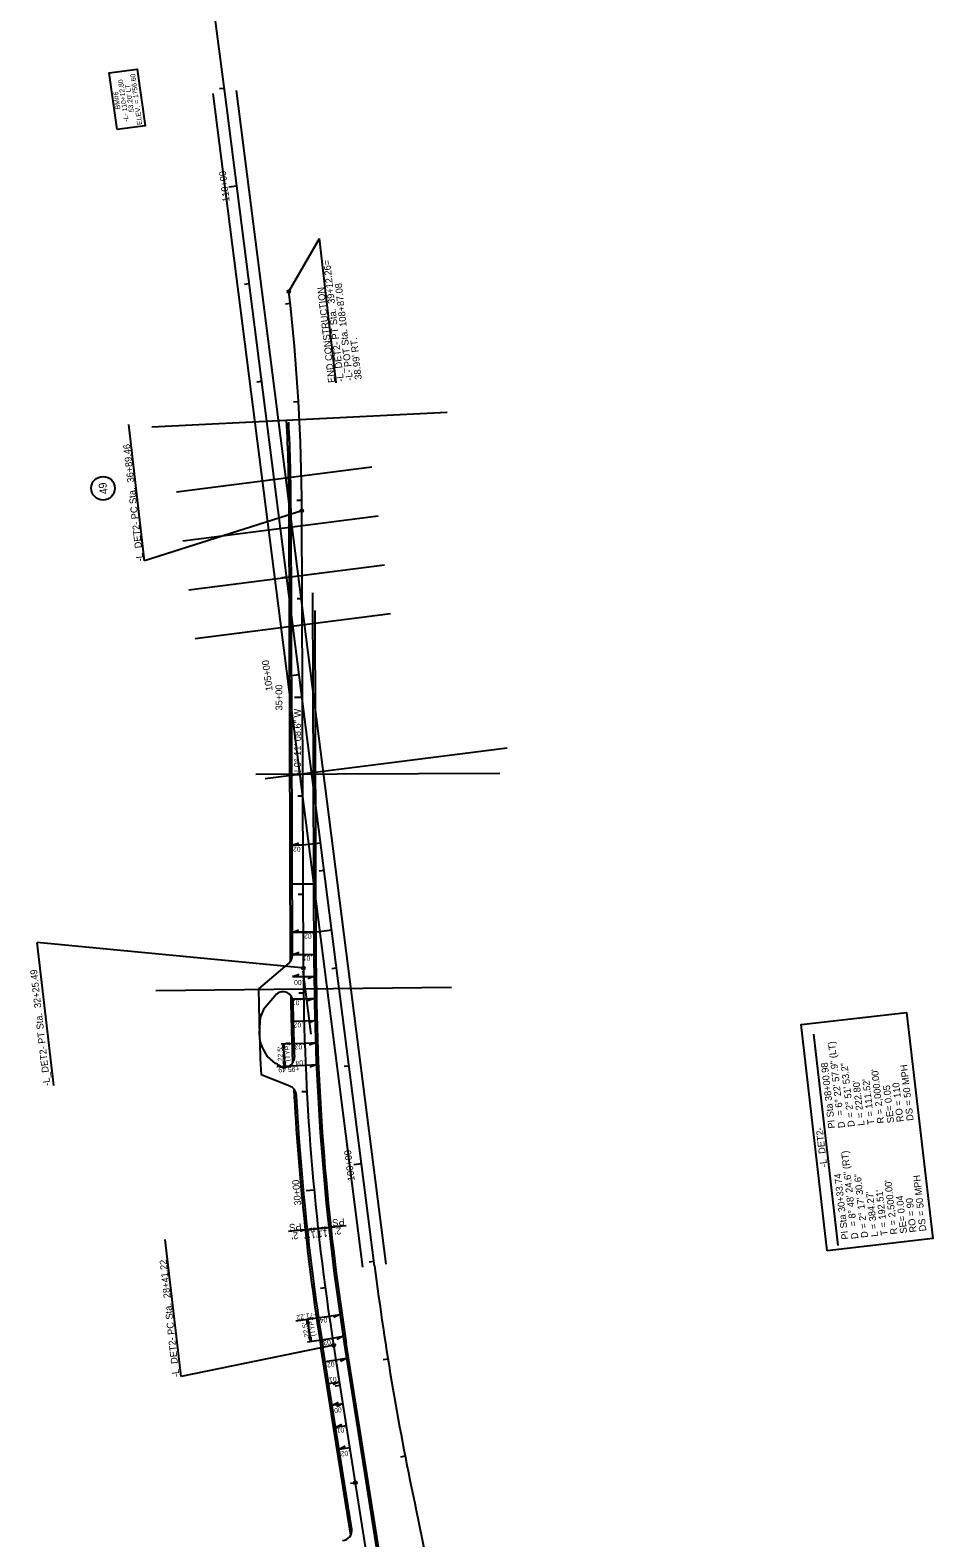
# Model space of a CAD drawing. Extents: x 473658 to 481584, y 489119 to 506230.
# Drawn here: x 477863 to 478779, y 496238 to 497767 of the extents above; entities that cross this region are included whole.
import ezdxf

# ---------------------------------------------------------------- set-up
doc = ezdxf.new("R2010")
doc.units = 0
for name, color, linetype in [('Default', 7, 'Continuous'), ('Prop Dimension', 7, 'Continuous'), ('Prop EOT', 7, 'Continuous'), ('Prop Grid Mask', 7, 'Continuous'), ('Prop Horizontal Alignment', 7, 'Continuous'), ('Prop Horizontal Alignment Curve and Spiral Data', 7, 'Continuous'), ('Prop Horizontal Alignment Direction Label', 7, 'Continuous'), ('Prop Horizontal Alignment Station Label', 7, 'Continuous'), ('Prop Horizontal Alignment Tick Label', 7, 'Continuous'), ('Prop Horizontal Alignment Tick Large', 7, 'Continuous'), ('Prop Horizontal Alignment Tick Small', 7, 'Continuous'), ('Prop Paved Shoulder', 7, 'Continuous'), ('Prop Superelevation  Arrow CELL', 7, 'Continuous'), ('Prop Superelevation Label', 7, 'Continuous'), ('Scratch_Level_5', 7, 'Continuous'), ('Scratch_Level_6', 7, 'Continuous'), ('Scratch_Level_9', 7, 'Continuous')]:
    doc.layers.add(name, color=color, linetype=linetype)

msp = doc.modelspace()

# ---------------------------------------------------------------- linework, layer by layer
at = {"layer": 'Default'}
msp.add_line((477937, 497302.6), (477937, 497302.6), dxfattribs=at)
msp.add_circle((477937, 497302.6), 12, dxfattribs=at)
at = {"layer": 'Prop Dimension'}
for p, q in [((478142.2, 496550.2), (478125, 496548.5)), ((478166.1, 496552.6), (478144.2, 496550.4)), ((478183.8, 496554.4), (478168, 496552.8))]:
    msp.add_line(p, q, dxfattribs=at)
for points in [[(478137.6, 496550.5), (478142.2, 496550.2), (478137.8, 496548.9), (478138.3, 496549.8)], [(478148.7, 496550.1), (478144.2, 496550.4), (478148.6, 496551.6), (478148.1, 496550.8)], [(478150.6, 496551.8), (478155.1, 496551.5), (478150.7, 496550.2), (478151.2, 496551.1)], [(478159.7, 496551.2), (478155.1, 496551.5), (478159.5, 496552.7), (478159, 496551.9)], [(478161.5, 496552.9), (478166.1, 496552.6), (478161.6, 496551.3), (478162.1, 496552.2)], [(478172.6, 496552.5), (478168, 496552.8), (478172.5, 496554), (478172, 496553.2)]]:
    msp.add_lwpolyline(points, close=True, dxfattribs=at)
at = {"layer": 'Prop EOT'}
for p, q in [((478129.2, 496828.8), (478127.7, 497279.7)), ((478151.2, 496815.8), (478150, 497196.6)), ((478125.7, 496821.2), (478094.8, 496794.9)), ((478113.1, 496789.4), (478099.8, 496773.7)), ((478114.1, 496718.2), (478112, 496719)), ((478126.6, 496696), (478097.3, 496707.6)), ((478184, 496280.1), (478160.1, 496431.4)), ((478319.9, 495562.1), (478181.8, 496434.9)), ((478189.3, 496246.6), (478184, 496280.1))]:
    msp.add_line(p, q, dxfattribs=at)
for points in [[(478099.8, 496773.7), (478096.6, 496766.2)], [(478112, 496719), (478103.8, 496726.1), (478102.4, 496728.3), (478099, 496734.4), (478096.3, 496741.3), (478095.7, 496749.8), (478096.6, 496766.2)]]:
    msp.add_lwpolyline(points, dxfattribs=at)
for centre, radius, start, end in [((476138.7, 497273.3), 1989, 0.1857, 2.7759), ((478119.2, 496828.8), 10, 310.4144, 0.1857), ((480640.2, 496823.9), 2489, 180.1857, 188.9925), ((480640.6, 496823.9), 2546, 180.6537, 182.6189), ((478119.6, 496781.8), 10, 0.9568, 130.4144), ((480640.2, 496823.9), 2511, 180.8982, 182.2432), ((478121.2, 496725.2), 10, 225.0261, 2.2432), ((478123, 496686.7), 10, 3.1201, 68.4309), ((480640.2, 496823.9), 2511, 183.1201, 188.9925), ((478179.5, 496245.1), 10, 272.076, 8.9925)]:
    msp.add_arc(centre, radius, start, end, dxfattribs=at)
at = {"layer": 'Prop Grid Mask'}
for points in [[(477951.2, 497666.5), (477943.2, 497723.9), (477971.6, 497727.9), (477979.6, 497670.4)], [(478671.8, 496528.9), (478645.2, 496758.4), (478752.3, 496770.8), (478778.9, 496541.3)]]:
    msp.add_lwpolyline(points, close=True, dxfattribs=at)
at = {"layer": 'Prop Horizontal Alignment'}
for p, q in [((478212.5, 496513.8), (478060.5, 497704.7)), ((478140.2, 496815.8), (478138.7, 497279.8)), ((478309.1, 495560.4), (478171, 496433.1)), ((478193, 496293.7), (478188.1, 496292.9)), ((478263.7, 496222.6), (478254.9, 496265.4))]:
    msp.add_line(p, q, dxfattribs=at)
for centre, radius, start, end in [((456237.5, 494918.9), 22000, 7.27466, 7.92268), ((476138.7, 497273.3), 2000, 0.1857, 6.5685), ((480640.2, 496823.9), 2500, 180.1857, 188.9925), ((481188.3, 496893.6), 3000, 187.2747, 192.0883)]:
    msp.add_arc(centre, radius, start, end, dxfattribs=at)
at = {"layer": 'Prop Horizontal Alignment Station Label'}
for p, q in [((478125.6, 497502.1), (478156.6, 497556.1)), ((478173.5, 497409.5), (478156.6, 497556.1)), ((477979, 497228.9), (477963.1, 497367.2)), ((478138.7, 497279.8), (477979, 497228.9)), ((478141.7, 496815.8), (477870.3, 496841.7)), ((477887, 496696.7), (477870.3, 496841.7)), ((478657.8, 496748.8), (478682.6, 496534.4)), ((478016.1, 496401.3), (478000.1, 496540.3)), ((478171, 496433.1), (478016.1, 496401.3))]:
    msp.add_line(p, q, dxfattribs=at)
for centre in [(478125.6, 497502.1), (478138.7, 497279.8), (478140.2, 496815.8), (478171, 496433.1), (478171, 496433.1), (478193, 496293.7)]:
    msp.add_circle(centre, 1.5, dxfattribs=at)
at = {"layer": 'Prop Horizontal Alignment Tick Large'}
for p, q in [((478072.7, 497609.1), (478064.7, 497608.1)), ((478136, 497113.2), (478128, 497112.2)), ((478139.4, 497090.3), (478131.4, 497090.3)), ((478199.3, 496617.2), (478191.3, 496616.2)), ((478151.1, 496590.6), (478143.2, 496589.9))]:
    msp.add_line(p, q, dxfattribs=at)
at = {"layer": 'Prop Horizontal Alignment Tick Small'}
for p, q in [((478060, 497708.3), (478055, 497707.7)), ((478085.3, 497509.9), (478080.4, 497509.3)), ((478127, 497489.9), (478122, 497489.3)), ((478098, 497410.8), (478093, 497410.1)), ((478135.3, 497390.2), (478130.3, 497389.9)), ((478110.6, 497311.6), (478105.7, 497310.9)), ((478138.7, 497290.3), (478133.7, 497290.3)), ((478123.3, 497212.4), (478118.3, 497211.7)), ((478139, 497190.3), (478134, 497190.3)), ((478148.6, 497014), (478143.7, 497013.3)), ((478139.7, 496990.3), (478134.7, 496990.3)), ((478161.3, 496914.8), (478156.3, 496914.1)), ((478140, 496890.3), (478135, 496890.3)), ((478174, 496815.6), (478169, 496815)), ((478140.5, 496790.3), (478135.5, 496790.2)), ((478186.6, 496716.4), (478181.7, 496715.8)), ((478143.8, 496690.4), (478138.8, 496690.1)), ((478211.9, 496518), (478207, 496517.4)), ((478162.5, 496491.3), (478157.5, 496490.6)), ((478226.1, 496419), (478221.2, 496418.2)), ((478177.4, 496392.4), (478172.5, 496391.6)), ((478243.6, 496320.6), (478238.7, 496319.6)), ((478193, 496293.7), (478188.1, 496292.9))]:
    msp.add_line(p, q, dxfattribs=at)
at = {"layer": 'Prop Paved Shoulder'}
for p, q in [((478127.2, 496822.8), (478125.7, 497279.7)), ((478153.2, 496815.8), (478152.1, 497178.5)), ((478183, 496273.9), (478158.1, 496431.1)), ((478321.9, 495562.4), (478183.8, 496435.2)), ((478188.3, 496240.4), (478183, 496273.9))]:
    msp.add_line(p, q, dxfattribs=at)
for centre, radius, start, end in [((476138.7, 497273.3), 1987, 0.1857, 2.8372), ((480640.2, 496823.9), 2487, 180.1857, 188.9925), ((480640.2, 496823.9), 2513, 180.8202, 182.3798), ((480640.2, 496823.9), 2513, 182.9835, 188.9925)]:
    msp.add_arc(centre, radius, start, end, dxfattribs=at)
at = {"layer": 'Prop Superelevation  Arrow CELL'}
for points in [[(478128.8, 496940.6), (478134.8, 496942.6), (478133.5, 496940.6)], [(478129.1, 496852.2), (478135.1, 496854.2), (478133.7, 496852.2)], [(478129.2, 496829.7), (478135.2, 496831.7), (478133.8, 496829.7)], [(478129.3, 496807.1), (478135.3, 496809.2), (478133.9, 496807.2)], [(478151.3, 496807.3), (478145.3, 496805.2), (478146.7, 496807.3)], [(478151.5, 496784.9), (478145.6, 496782.8), (478146.9, 496784.8)], [(478152, 496762.5), (478146, 496760.3), (478147.4, 496762.4)], [(478119.4, 496734.6), (478120.1, 496739.1), (478120.9, 496734.6), (478120.1, 496735.1)], [(478152.6, 496740.1), (478146.7, 496737.9), (478148, 496739.9)], [(478121.6, 496720.9), (478121, 496716.3), (478120, 496720.8), (478120.8, 496720.3)], [(478153.5, 496717.7), (478147.6, 496715.5), (478148.9, 496717.5)], [(478144.1, 496455), (478144.2, 496459.6), (478145.7, 496455.2), (478144.8, 496455.7)], [(478177.3, 496464.4), (478171.7, 496461.5), (478172.8, 496463.7)], [(478147.8, 496441.7), (478147.7, 496437.1), (478146.2, 496441.5), (478147.1, 496441)], [(478180.7, 496442.2), (478175, 496439.3), (478176.1, 496441.5)], [(478184.2, 496420), (478178.6, 496417.1), (478179.6, 496419.3)], [(478176.8, 496396.1), (478171.2, 496393.2), (478172.3, 496395.4)], [(478169.5, 496372.2), (478175.1, 496375.1), (478174, 496372.9)], [(478180.3, 496373.9), (478174.7, 496371), (478175.8, 496373.2)], [(478173, 496349.9), (478178.6, 496352.8), (478177.6, 496350.7)], [(478176.5, 496327.7), (478182.1, 496330.6), (478181.1, 496328.4)]]:
    msp.add_lwpolyline(points, close=True, dxfattribs=at)
at = {"layer": 'Prop Superelevation Label'}
for p, q in [((478128.8, 496940.6), (478139.8, 496940.7)), ((478129.1, 496852.2), (478151.1, 496852.2)), ((478129.2, 496829.7), (478151.2, 496829.7)), ((478129.3, 496807.1), (478151.3, 496807.3)), ((478129.5, 496784.5), (478140.5, 496784.7)), ((478140.5, 496784.7), (478151.5, 496784.9)), ((478130, 496761.9), (478141, 496762.2)), ((478141, 496762.2), (478152, 496762.5)), ((478117.6, 496738.9), (478141.6, 496739.7)), ((478141.6, 496739.7), (478152.6, 496740.1)), ((478113.4, 496716), (478142.5, 496717.2)), ((478142.5, 496717.2), (478153.5, 496717.7)), ((478132.6, 496457.9), (478166.4, 496462.8)), ((478166.4, 496462.8), (478177.3, 496464.4)), ((478144.5, 496436.6), (478169.8, 496440.5)), ((478169.8, 496440.5), (478180.7, 496442.2)), ((478162.4, 496416.6), (478173.3, 496418.3)), ((478173.3, 496418.3), (478184.2, 496420)), ((478166, 496394.4), (478176.8, 496396.1)), ((478169.5, 496372.2), (478180.3, 496373.9)), ((478173, 496349.9), (478183.9, 496351.7)), ((478176.5, 496327.7), (478187.4, 496329.4))]:
    msp.add_line(p, q, dxfattribs=at)
for centre, start, end in [((479146.7, 496769), 181.6837, 182.9409), ((479161.2, 496603.6), 188.0646, 189.331)]:
    msp.add_arc(centre, 1027.1, start, end, dxfattribs=at)
at = {"layer": 'Scratch_Level_5'}
for p, q in [((477986.5, 497364.8), (478286.1, 497379.7)), ((477990.4, 496793.1), (478290.4, 496796.5))]:
    msp.add_line(p, q, dxfattribs=at)
at = {"layer": 'Scratch_Level_6'}
for p, q in [((478224.4, 496515.3), (478072.4, 497706.2)), ((478200.6, 496512.2), (478048.6, 497703.1)), ((478101.5, 497008), (478347, 497039.3)), ((478092.1, 497012.7), (478339.6, 497013.5)), ((478139.8, 496940.7), (478157.7, 496942.9)), ((478139.8, 496940.7), (478128.8, 496940.6)), ((478151, 496900.9), (478129, 496900.8)), ((478151.1, 496852.2), (478129.1, 496852.2)), ((478151.1, 496852.2), (478169, 496854.5)), ((478148.2, 496748.7), (478140.1, 496812.6))]:
    msp.add_line(p, q, dxfattribs=at)
at = {"layer": 'Scratch_Level_9'}
for p, q in [((478011.4, 497298.9), (478209.8, 497324.2)), ((478017.8, 497249.3), (478216.2, 497274.6)), ((478024.1, 497199.7), (478222.5, 497225)), ((478030.4, 497150.1), (478228.8, 497175.4))]:
    msp.add_line(p, q, dxfattribs=at)

# ---------------------------------------------------------------- texts
at = {"layer": 'Default'}
for s, height, p in [('ELEV. = 1756.60', 5, (477976.7, 497671.6)), ('-L- 110+12.80', 5, (477963, 497674.9)), ("53.20' LT", 5, (477968.3, 497684.4)), ('BM#6', 5, (477954.6, 497687.4)), ('49', 8, (477941.8, 497297.1))]:
    msp.add_text(s, height=height, rotation=97.9227, dxfattribs=at).set_placement(p)
at = {"layer": 'Prop Dimension'}
for s, p in [('PS', (478181.7, 496562)), ('PS', (478138, 496557.2)), ("2'", (478134.7, 496548)), ("11'", (478152.5, 496549)), ("11'", (478164.6, 496550.2)), ("2'", (478178.4, 496552.8))]:
    msp.add_text(s, height=7, rotation=185.7513, dxfattribs=at).set_placement(p)
at = {"layer": 'Prop Horizontal Alignment Curve and Spiral Data'}
for s, rotation, p in [('= 6%%d 22\' 57.9" (LT)', 96.6074, (478688.1, 496666.6)), ('PI Sta 38+00.98', 96.6074, (478679.9, 496653.4)), ('D = 2%%d 51\' 53.2"', 96.6074, (478699.8, 496655)), ("R = 2,000.00'", 96.6074, (478729.6, 496658.5)), ('DS = 50 MPH', 96.5773, (478759.4, 496661.2)), ("L = 222.80'", 96.6074, (478709.7, 496656.2)), ("T = 111.52'", 96.6074, (478719.7, 496657.3)), ('SE= 0.05', 96.5773, (478739.7, 496658.9)), ('RO = 110', 96.5773, (478749.3, 496660)), ('D', 96.6074, (478689.9, 496653.9)), ('= 8%%d 48\' 24.6" (RT)', 96.6074, (478701.6, 496554.1)), ('PI Sta 30+33.74', 96.6074, (478693.4, 496540.8)), ('D = 2%%d 17\' 30.6"', 96.6074, (478713.3, 496542.5)), ('DS = 50 MPH', 96.5773, (478772.4, 496549.1)), ("T = 192.51'", 96.6074, (478733.2, 496544.8)), ("R = 2,500.00'", 96.6074, (478743.1, 496545.9)), ("L = 384.27'", 96.6074, (478723.3, 496543.6)), ('SE= 0.04', 96.5773, (478752.8, 496546.9)), ('RO = 90', 96.5773, (478762.4, 496548)), ('D', 96.6074, (478703.4, 496541.3))]:
    msp.add_text(s, height=7, rotation=rotation, dxfattribs=at).set_placement(p)
at = {"layer": 'Prop Horizontal Alignment Direction Label'}
msp.add_text('N 0%%d 11\' 08.6" W', height=7, rotation=90.1857, dxfattribs=at).set_placement((478137.9, 497010.2))
at = {"layer": 'Prop Horizontal Alignment Station Label'}
for s, rotation, p in [('-L_DET2- PT Sta.  39+12.26=', 96.5773, (478181.4, 497411.1)), ('-L- POT Sta. 108+87.08', 96.5773, (478190.5, 497412.1)), ('END CONSTRUCTION', 96.5773, (478172.4, 497410)), ("38.99' RT.", 96.5773, (478199.5, 497413.2)), ('-L_DET2- PC Sta.  36+89.46', 96.5773, (477977.9, 497228.7)), ('-L_DET2- PT Sta.  32+25.49', 96.5773, (477883.5, 496696.6)), ('-L_DET2-', 96.5773, (478671.7, 496614.3)), ('-L_DET2- PC Sta.  28+41.22', 96.3635, (478014.5, 496401.2))]:
    msp.add_text(s, height=7, rotation=rotation, dxfattribs=at).set_placement(p)
at = {"layer": 'Prop Horizontal Alignment Tick Label'}
for s, rotation, p in [('110+00', 97.2747, (478065.5, 497593.7)), ('105+00', 97.2747, (478109.1, 497097.4)), ('35+00', 90.1857, (478119, 497077.2)), ('100+00', 97.2747, (478192.4, 496600.3)), ('30+00', 95.3536, (478138.2, 496575.2))]:
    msp.add_text(s, height=7, rotation=rotation, dxfattribs=at).set_placement(p)
at = {"layer": 'Prop Superelevation Label'}
for s, rotation, p in [('.02', 180.1857, (478139.3, 496938.9)), ('.02', 180.1857, (478150.6, 496850.8)), ('.01', 180.1857, (478149.2, 496828.3)), ('.00', 180.3825, (478140.4, 496803.7)), ('.01', 180.8982, (478138.1, 496783.2)), ('.02', 181.4139, (478140, 496760.7)), ("22.5'", 90.7137, (478119.3, 496721.3)), ('(TYP.)', 90.7137, (478126.6, 496721.2)), ('.03', 181.9295, (478141, 496738.5)), ('+95.49', 182.2856, (478136.1, 496715.8)), ('.04', 182.4452, (478141.7, 496722.3)), ('+71.22', 188.6611, (478154, 496466.8)), ("22.5'", 98.6611, (478146.1, 496441.7)), ('(TYP.)', 98.6611, (478152.6, 496442.5)), ('.04', 188.305, (478166.1, 496461.8)), ('.03', 188.8207, (478169.6, 496439.3)), ('.02', 188.9926, (478173.3, 496416.9)), ('.01', 188.9926, (478175.4, 496401.6)), ('.00', 188.9926, (478180.6, 496370.6)), ('.01', 188.9926, (478183.2, 496350.2)), ('.02', 188.9926, (478187.3, 496326.6))]:
    msp.add_text(s, height=5, rotation=rotation, dxfattribs=at).set_placement(p)

doc.saveas('drawing.dxf')
